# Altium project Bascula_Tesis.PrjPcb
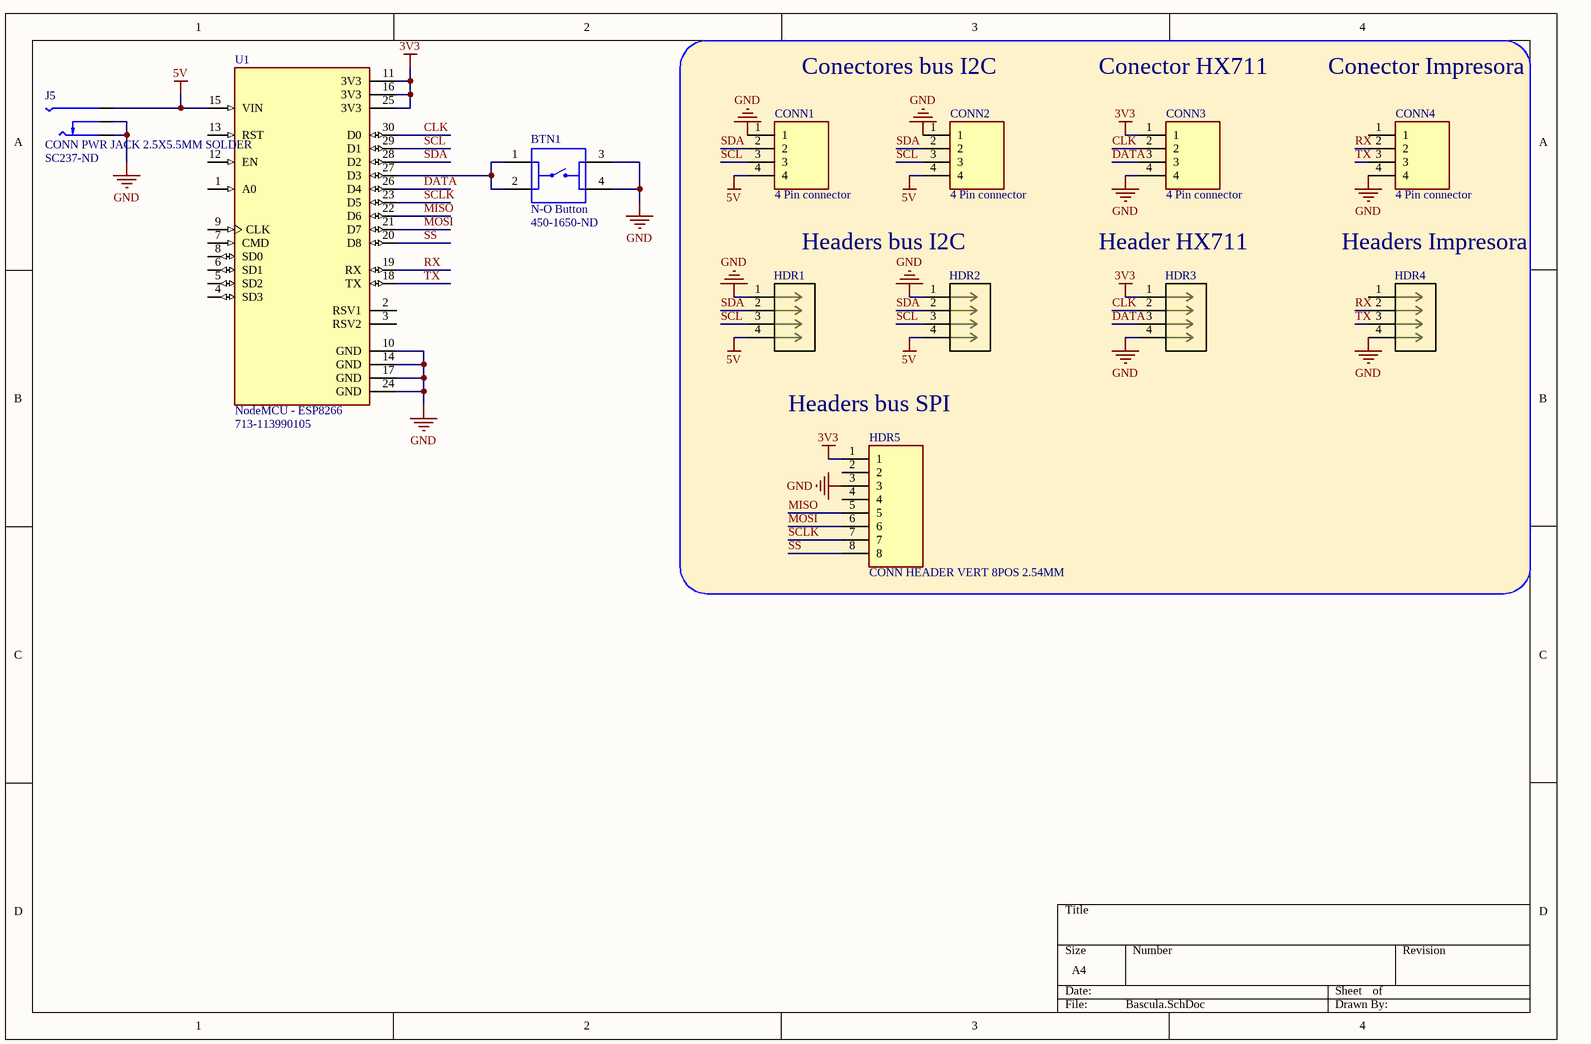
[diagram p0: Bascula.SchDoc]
1 sheet, 12 parts. Net scope: global (net labels, ports and power ports of the same name join across sheets).
Board file: Bascula.PcbDoc

## Sheet Bascula.SchDoc
size A4

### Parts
BTN1  N-O Button  Supplier Part Number 1: 450-1650-ND  [1825910-6]
CONN1  4 Pin connector  [440054-4]
CONN2  4 Pin connector  [440054-4]
CONN3  4 Pin connector  [440054-4]
CONN4  4 Pin connector  [440054-4]
HDR1  CONN HEADER VERT 4POS 2.54MM  [825433-4]  (value not drawn)
HDR2  CONN HEADER VERT 4POS 2.54MM  [825433-4]  (value not drawn)
HDR3  CONN HEADER VERT 4POS 2.54MM  [825433-4]  (value not drawn)
HDR4  CONN HEADER VERT 4POS 2.54MM  [825433-4]  (value not drawn)
HDR5  CONN HEADER VERT 8POS 2.54MM  [640454-8]
J5  CONN PWR JACK 2.5X5.5MM SOLDER  Supplier Part Number 1: SC237-ND  [RAPC712X]
U1  NodeMCU - ESP8266  Supplier Part Number 1: 713-113990105  [ZC563900]

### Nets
3V3: CONN3.1 HDR3.1 HDR5.1 U1.11(3V3) U1.16(3V3) U1.25(3V3)
5V: CONN1.4 CONN2.4 HDR1.4 HDR2.4 J5.PIN U1.15(VIN)
GND: BTN1.3 BTN1.4 CONN1.1 CONN2.1 CONN3.4 CONN4.4 HDR1.1 HDR2.1 HDR3.4 HDR4.4 HDR5.3 J5.SHUNT J5.SLEEVE U1.10(GND) U1.14(GND) U1.17(GND) U1.24(GND)
CLK: CONN3.2 HDR3.2 U1.30(D0)
DATA: CONN3.3 HDR3.3 U1.26(D4)
MISO: HDR5.5 U1.22(D6)
MOSI: HDR5.6 U1.21(D7)
RX: CONN4.2 HDR4.2 U1.19(RX)
SCL: CONN1.3 CONN2.3 HDR1.3 HDR2.3 U1.29(D1)
SCLK: HDR5.7 U1.23(D5)
SDA: CONN1.2 CONN2.2 HDR1.2 HDR2.2 U1.28(D2)
SS: HDR5.8 U1.20(D8)
TX: CONN4.3 HDR4.3 U1.18(TX)
NetBTN1_1: BTN1.1 BTN1.2 U1.27(D3)

Not connected (* = marked no-connect by the designer): CONN4 1; HDR4 1; HDR5 2 4; U1 1(A0) 2(RSV1) 3(RSV2) 4(SD3) 5(SD2) 6(SD1) 7(CMD) 8(SD0) 9(CLK) 12(EN) 13(RST)

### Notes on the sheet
- Conectores bus I2C
- Conector HX711
- Conector Impresora
- Headers bus I2C
- Header HX711
- Headers Impresora
- Headers bus SPI

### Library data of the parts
BTN1 = 1825910-6: Interruptores táctiles SPST-NO (Normalmente abierto) Activación superior Orificio pasante. SWITCH TACTILE SPST-NO 0.05A 24V; Configuration_Pole-Throw: Single Pole - Single Throw; MF: TE Connectivity; Contact_Current_Rating: 50 mA
CONN1-CONN4 = 440054-4: Cabezal de conector Orificio pasante 4 posiciones 0.079" (2.00mm). / Complementario con 1735447-4.; MF: TE Connectivity
HDR1-HDR4 = 825433-4: Cabezal de conector Orificio pasante 4 posiciones 0.100" (2.54mm); MF: TE Connectivity; Number of Positions: 4; Connector Type: Plug,Header,Pin; Gender: Male; Current Rating: 3A; Board Standoff: No (Without); High Speed Serial Data Connector: No; PCB Mount Retention: Without; PCB Mounting Orientation: Vertical; Contact Current Rating: 5A; Contact Post Length: 0.1259inch; Plating Thickness: 2.5um; Approvals: CSA
HDR5 = 640454-8: Cabezal de conector Orificio pasante 8 posiciones 0.100" (2.54mm). / Complementario con 3-644540-8.; MF: TE Connectivity; Underplate Material: Nickel; Number of Contacts: 8; Connector Type: Plug,Header,Pin; Mating Alignment: No (Without); Current Rating: 5A; Max Voltage Rating (AC): 250V; Connector System: Wire-to-Board; PCB Mount Retention: Without; Contact Resistance: 6mR; PCB Mounting Orientation: Vertical; Contact Style: Straight; Plating Thickness: 3.81um; PCB Thickness: 0.063inch; Contact Post Length: 3.56mm; Approvals: CSA
J5 = RAPC712X: Conn DC Power PL 2 POS Solder RA Thru-Hole 3 Terminal 1 Port Bulk; MF: Switchcraft; Number of Terminals/Pins: 3; Body Material: Thermoplastic; Gender: Male; Shielding: Unshielded; Current Rating: 5A; Connector Type: Jack,Power; Insulation Resistance: 30MR; Number of Ports: 1; Number of Contacts: 2; Pin Diameter: 2.5mm
U1 = ZC563900: NodeMcu Lua ESP8266 WIFI Internet of Things Network Development Module Board; Manufacturer_Name: YKS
